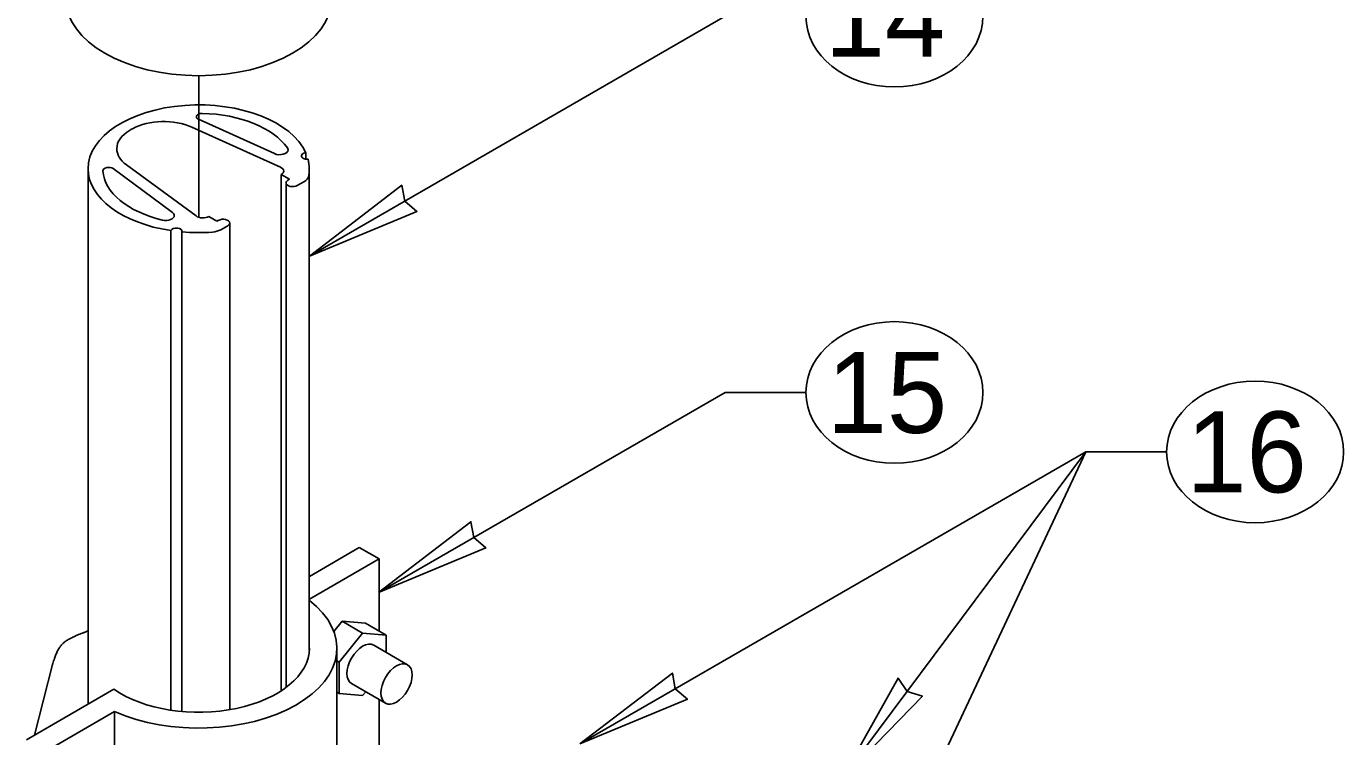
# Model space of a CAD drawing. Extents: x 99862 to 104211, y 98939 to 105076.
# Drawn here: x 101127.6 to 101388.1, y 100413.2 to 100553.6 of the extents above; entities that cross this region are included whole.
import ezdxf

# ---------------------------------------------------------------- set-up
doc = ezdxf.new("R2010")
doc.units = 0
for name, color, linetype in [('Default', 7, 'Continuous'), ('Level 13', 7, 'Continuous'), ('Level 15', 7, 'Continuous'), ('Level 20', 7, 'Continuous')]:
    doc.layers.add(name, color=color, linetype=linetype)

msp = doc.modelspace()

# ---------------------------------------------------------------- linework, layer by layer
at = {"layer": 'Default'}
for p, q in [((101160.33, 100533.7), (101177.88, 100525.76)), ((101176.66, 100528.45), (101161.66, 100535.24)), ((101182.87, 100527.37), (101182.87, 100528.63)), ((101161.18, 100516.12), (101147.42, 100526.25)), ((101139.83, 100525.46), (101139.83, 100419.6)), ((101144.76, 100525.48), (101156.52, 100516.82)), ((101178.03, 100422.23), (101178.03, 100524.31)), ((101178.03, 100524.31), (101179.65, 100523.37)), ((101179.65, 100523.37), (101179.35, 100523.2)), ((101183.57, 100430.32), (101183.57, 100525.46)), ((101178.97, 100522.67), (101178.97, 100422.88)), ((101181.19, 100522.13), (101182.6, 100522.95)), ((101165.31, 100515.09), (101163.69, 100516.03)), ((101165.61, 100515.27), (101165.31, 100515.09)), ((101156.2, 100418.41), (101156.2, 100513.24)), ((101158.4, 100418.15), (101158.4, 100512.98)), ((101166.05, 100513.39), (101167.46, 100514.2)), ((101167.84, 100418.51), (101167.84, 100514.73))]:
    msp.add_line(p, q, dxfattribs=at)
for centre, major_axis, start_param, end_param in [((101161.7, 100525.46), (-21.87, 0), 3.395646, 6.283185), ((101162.36, 100535.75), (1.12, 0), 1.534049, 3.141593), ((101161.7, 100525.46), (18.96, 0), 0.38598, 1.533953), ((101154.8, 100529.62), (8.97, 0), 0.905848, 2.333979), ((101162.36, 100535.75), (1.12, 0), 3.141593, 4.047441), ((101154.48, 100529.44), (8.97, 0), 2.378443, 3.141593), ((101161.7, 100525.46), (18.96, 0), 2.333979, 2.37841), ((101154.48, 100529.44), (8.97, 0), 3.141593, 3.806541), ((101177.7, 100529.21), (1.68, 0), 4.047441, 6.283185), ((101177.7, 100529.21), (1.68, 0), 0, 0.38598), ((101183.12, 100528), (1.12, 0), 1.799206, 3.141593), ((101143.88, 100525.08), (1.12, 0), 0.664948, 3.141593), ((101176.84, 100525), (1.68, 0), 0, 0.905848), ((101183.12, 100528), (1.12, 0), 3.141593, 4.889511), ((101161.7, 100525.46), (-21.87, 0), 3.141593, 3.293071), ((101161.7, 100525.46), (-21.87, 0), 0, 1.316743), ((101143.88, 100525.08), (1.12, 0), 3.141593, 3.178442), ((101161.7, 100525.46), (18.96, 0), 3.178442, 4.326409), ((101176.84, 100525), (1.68, 0), 5.497787, 6.283185), ((101180.27, 100522.67), (-1.3, 0), 5.497787, 6.283185), ((101180.62, 100524.09), (-2.8, 0), 2.356194, 3.017093), ((101161.7, 100525.46), (-21.87, 0), 3.017093, 3.141593), ((101180.27, 100522.67), (-1.3, 0), 0, 2.356195), ((101155.2, 100516.22), (1.68, 0), 4.326409, 6.283185), ((101155.2, 100516.22), (1.68, 0), 6.283185, 6.948133), ((101162.5, 100516.72), (1.68, 0), 3.806541, 5.497787), ((101166.53, 100514.73), (-1.3, 0), 3.141593, 5.497787), ((101157.29, 100513.09), (1.12, 0), 6.106063, 9.196368), ((101161.7, 100525.46), (-21.87, 0), 1.419318, 1.695296), ((101164.07, 100514.54), (-2.8, 0), 1.695296, 2.356194), ((101166.53, 100514.73), (-1.3, 0), 2.356194, 3.141593)]:
    msp.add_ellipse(centre, major_axis=major_axis, ratio=0.57735, start_param=start_param, end_param=end_param, dxfattribs=at)
at = {"layer": 'Level 13'}
msp.add_ellipse((101161.7, 100559.01), major_axis=(26.25, 0), ratio=0.57735, start_param=3.141593, end_param=6.283185, dxfattribs=at)
at = {"layer": 'Level 15'}
for p, q in [((101183.58, 100508.19), (101265.76, 100555.63)), ((101161.7, 100515.86), (101161.7, 100543.85)), ((101197.24, 100441.67), (101265.76, 100481.23)), ((101281.76, 100481.23), (101265.76, 100481.23)), ((101237.08, 100411.74), (101337.07, 100469.47)), ((101279.67, 100347.05), (101337.07, 100469.47)), ((101288.74, 100404.66), (101337.02, 100469.41)), ((101353.07, 100469.47), (101337.07, 100469.47)), ((101193.46, 100450.57), (101183.58, 100444.86)), ((101197.37, 100448.32), (101193.46, 100450.57)), ((101183.58, 100440.35), (101197.37, 100448.32)), ((101197.37, 100434.04), (101197.37, 100448.32)), ((101190.06, 100435.99), (101188.42, 100433.95)), ((101194.7, 100435.58), (101190.06, 100435.99)), ((101194.11, 100433.65), (101190.06, 100435.99)), ((101198.75, 100433.24), (101194.7, 100435.58)), ((101194.11, 100433.65), (101189.47, 100427.88)), ((101198.75, 100433.24), (101194.11, 100433.65)), ((101198.75, 100429.84), (101198.75, 100433.24)), ((101189.03, 100401.39), (101189.03, 100430.64)), ((101203.01, 100427.38), (101196.3, 100431.25)), ((101132.82, 100427.41), (101129.24, 100413.49)), ((101189.47, 100427.88), (101189.03, 100428.14)), ((101189.47, 100427.88), (101189.47, 100421.69)), ((101144.91, 100422.54), (101127.63, 100412.56)), ((101189.47, 100421.69), (101189.03, 100421.95)), ((101189.47, 100421.69), (101194.11, 100421.28)), ((101191.93, 100423.68), (101198.63, 100419.8)), ((101194.11, 100421.28), (101194.74, 100422.05)), ((101197.37, 100400.25), (101197.37, 100420.53)), ((101131.53, 100410.31), (101145.07, 100418.12)), ((101145.07, 100404.57), (101145.07, 100418.12))]:
    msp.add_line(p, q, dxfattribs=at)
for points in [[(101183.58, 100508.19), (101204.84, 100517.01), (101202.43, 100519.07), (101201.86, 100522.19)], [(101197.24, 100441.67), (101218.5, 100450.5), (101216.09, 100452.56), (101215.51, 100455.67)], [(101237.08, 100411.74), (101258.34, 100420.57), (101255.93, 100422.63), (101255.36, 100425.74)], [(101288.74, 100404.66), (101304.78, 100421.17), (101301.76, 100422.11), (101299.99, 100424.74)]]:
    msp.add_lwpolyline(points, close=True, dxfattribs=at)
for centre, major_axis, start_param, end_param in [((101161.7, 100430.64), (27.33, 0), 4.057953, 6.925784), ((101194.11, 100427.46), (2.19, 3.79), 0.000003, 3.141593), ((101161.7, 100430.64), (21.88, 0), 3.837484, 6.283185)]:
    msp.add_ellipse(centre, major_axis=major_axis, ratio=0.57735, start_param=start_param, end_param=end_param, dxfattribs=at)
msp.add_ellipse((101200.82, 100423.59), major_axis=(2.19, 3.79), ratio=0.57735, dxfattribs=at)
msp.add_open_spline([(101139.83, 100434.05), (101136.4, 100432.87), (101133.65, 100430.63), (101132.82, 100427.41)], degree=2, dxfattribs=at)
at = {"layer": 'Level 20'}
for centre in [(101299.26, 100555.63), (101299.26, 100481.23), (101370.57, 100469.47)]:
    msp.add_ellipse(centre, major_axis=(-17.5, 0), ratio=0.8, dxfattribs=at)

# ---------------------------------------------------------------- texts
for s, p in [('14', (101285.48, 100547.63)), ('15', (101285.88, 100473.23)), ('16', (101356.97, 100461.47))]:
    msp.add_text(s, height=16, dxfattribs=at).set_placement(p)

doc.saveas('drawing.dxf')
